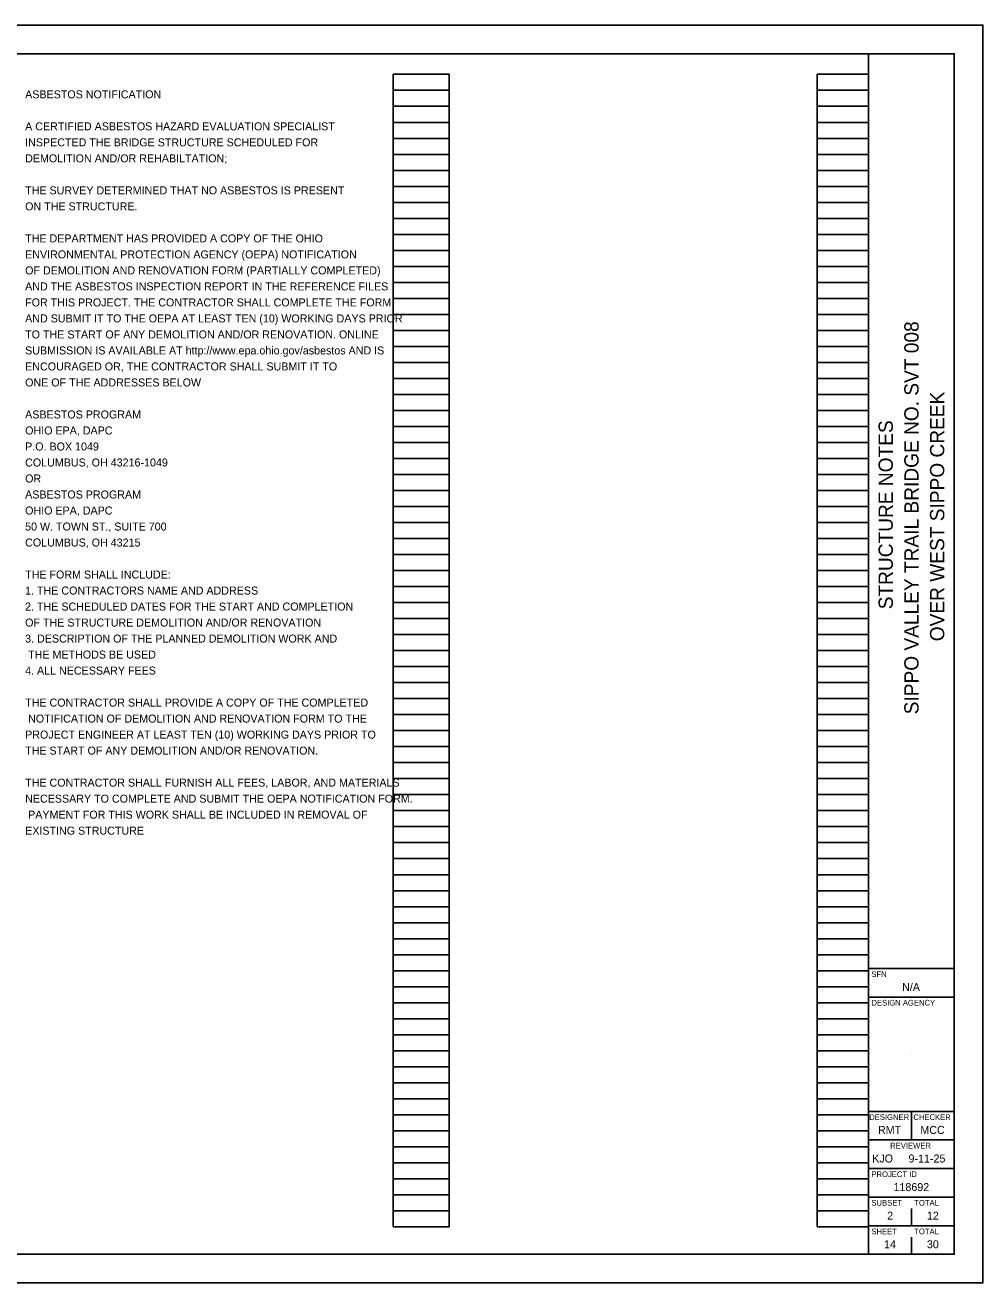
# Model space of a CAD drawing. Extents: x 0 to 34, y 0 to 22.
# Drawn here: x 17.24 to 34, y 0 to 22 of the extents above; entities that cross this region are included whole.
import ezdxf

# ---------------------------------------------------------------- set-up
doc = ezdxf.new("R2010")
doc.units = 0
for name, color, linetype in [('SH_Border', 7, 'Continuous'), ('SH_Cut_Line', 7, 'Continuous'), ('SH_Data', 7, 'Continuous'), ('SH_Text', 7, 'Continuous')]:
    doc.layers.add(name, color=color, linetype=linetype)

msp = doc.modelspace()

# ---------------------------------------------------------------- linework, layer by layer
at = {"layer": 'SH_Border'}
for p, q in [((32, 0.5), (32, 21.5)), ((32, 5.5), (33.5, 5.5)), ((32, 5), (33.5, 5)), ((32, 3), (33.5, 3)), ((32.75, 3), (32.75, 2.5)), ((32, 2.5), (33.5, 2.5)), ((32, 2), (33.5, 2)), ((32, 1.5), (33.5, 1.5)), ((32, 1), (33.5, 1))]:
    msp.add_line(p, q, dxfattribs=at)
msp.add_lwpolyline([(1.5, 21.5), (33.5, 21.5), (33.5, 0.5), (1.5, 0.5)], close=True, dxfattribs=at)
at = {"layer": 'SH_Cut_Line'}
msp.add_lwpolyline([(0, 0), (34, 0), (34, 22), (0, 22)], close=True, dxfattribs=at)
at = {"layer": 'SH_Data'}
for p, q in [((23.68, 0.98), (23.68, 21.14)), ((23.68, 21.14), (24.66, 21.14)), ((24.66, 0.98), (24.66, 21.14)), ((31.1, 0.98), (31.1, 21.14)), ((31.1, 21.14), (32, 21.14)), ((32, 0.98), (32, 21.14)), ((23.68, 20.86), (24.66, 20.86)), ((31.1, 20.86), (32, 20.86)), ((23.68, 20.58), (24.66, 20.58)), ((31.1, 20.58), (32, 20.58)), ((23.68, 20.3), (24.66, 20.3)), ((31.1, 20.3), (32, 20.3)), ((23.68, 20.02), (24.66, 20.02)), ((31.1, 20.02), (32, 20.02)), ((23.68, 19.74), (24.66, 19.74)), ((31.1, 19.74), (32, 19.74)), ((23.68, 19.46), (24.66, 19.46)), ((31.1, 19.46), (32, 19.46)), ((23.68, 19.18), (24.66, 19.18)), ((31.1, 19.18), (32, 19.18)), ((23.68, 18.9), (24.66, 18.9)), ((31.1, 18.9), (32, 18.9)), ((23.68, 18.62), (24.66, 18.62)), ((31.1, 18.62), (32, 18.62)), ((23.68, 18.34), (24.66, 18.34)), ((31.1, 18.34), (32, 18.34)), ((23.68, 18.06), (24.66, 18.06)), ((31.1, 18.06), (32, 18.06)), ((23.68, 17.78), (24.66, 17.78)), ((31.1, 17.78), (32, 17.78)), ((23.68, 17.5), (24.66, 17.5)), ((31.1, 17.5), (32, 17.5)), ((23.68, 17.22), (24.66, 17.22)), ((31.1, 17.22), (32, 17.22)), ((23.68, 16.94), (24.66, 16.94)), ((31.1, 16.94), (32, 16.94)), ((23.68, 16.66), (24.66, 16.66)), ((31.1, 16.66), (32, 16.66)), ((23.68, 16.38), (24.66, 16.38)), ((31.1, 16.38), (32, 16.38)), ((23.68, 16.1), (24.66, 16.1)), ((31.1, 16.1), (32, 16.1)), ((23.68, 15.82), (24.66, 15.82)), ((31.1, 15.82), (32, 15.82)), ((23.68, 15.54), (24.66, 15.54)), ((31.1, 15.54), (32, 15.54)), ((23.68, 15.26), (24.66, 15.26)), ((31.1, 15.26), (32, 15.26)), ((23.68, 14.98), (24.66, 14.98)), ((31.1, 14.98), (32, 14.98)), ((23.68, 14.7), (24.66, 14.7)), ((31.1, 14.7), (32, 14.7)), ((23.68, 14.42), (24.66, 14.42)), ((31.1, 14.42), (32, 14.42)), ((23.68, 14.14), (24.66, 14.14)), ((31.1, 14.14), (32, 14.14)), ((23.68, 13.86), (24.66, 13.86)), ((31.1, 13.86), (32, 13.86)), ((23.68, 13.58), (24.66, 13.58)), ((31.1, 13.58), (32, 13.58)), ((23.68, 13.3), (24.66, 13.3)), ((31.1, 13.3), (32, 13.3)), ((23.68, 13.02), (24.66, 13.02)), ((31.1, 13.02), (32, 13.02)), ((23.68, 12.74), (24.66, 12.74)), ((31.1, 12.74), (32, 12.74)), ((23.68, 12.46), (24.66, 12.46)), ((31.1, 12.46), (32, 12.46)), ((23.68, 12.18), (24.66, 12.18)), ((31.1, 12.18), (32, 12.18)), ((23.68, 11.9), (24.66, 11.9)), ((31.1, 11.9), (32, 11.9)), ((23.68, 11.62), (24.66, 11.62)), ((31.1, 11.62), (32, 11.62)), ((23.68, 11.34), (24.66, 11.34)), ((31.1, 11.34), (32, 11.34)), ((23.68, 11.06), (24.66, 11.06)), ((31.1, 11.06), (32, 11.06)), ((23.68, 10.78), (24.66, 10.78)), ((31.1, 10.78), (32, 10.78)), ((23.68, 10.5), (24.66, 10.5)), ((31.1, 10.5), (32, 10.5)), ((23.68, 10.22), (24.66, 10.22)), ((31.1, 10.22), (32, 10.22)), ((23.68, 9.94), (24.66, 9.94)), ((31.1, 9.94), (32, 9.94)), ((23.68, 9.66), (24.66, 9.66)), ((31.1, 9.66), (32, 9.66)), ((23.68, 9.38), (24.66, 9.38)), ((31.1, 9.38), (32, 9.38)), ((23.68, 9.1), (24.66, 9.1)), ((31.1, 9.1), (32, 9.1)), ((23.68, 8.82), (24.66, 8.82)), ((31.1, 8.82), (32, 8.82)), ((23.68, 8.54), (24.66, 8.54)), ((31.1, 8.54), (32, 8.54)), ((23.68, 8.26), (24.66, 8.26)), ((31.1, 8.26), (32, 8.26)), ((23.68, 7.98), (24.66, 7.98)), ((31.1, 7.98), (32, 7.98)), ((23.68, 7.7), (24.66, 7.7)), ((31.1, 7.7), (32, 7.7)), ((23.68, 7.42), (24.66, 7.42)), ((31.1, 7.42), (32, 7.42)), ((23.68, 7.14), (24.66, 7.14)), ((31.1, 7.14), (32, 7.14)), ((23.68, 6.86), (24.66, 6.86)), ((31.1, 6.86), (32, 6.86)), ((23.68, 6.58), (24.66, 6.58)), ((31.1, 6.58), (32, 6.58)), ((23.68, 6.3), (24.66, 6.3)), ((31.1, 6.3), (32, 6.3)), ((23.68, 6.02), (24.66, 6.02)), ((31.1, 6.02), (32, 6.02)), ((23.68, 5.74), (24.66, 5.74)), ((31.1, 5.74), (32, 5.74)), ((23.68, 5.46), (24.66, 5.46)), ((31.1, 5.46), (32, 5.46)), ((23.68, 5.18), (24.66, 5.18)), ((31.1, 5.18), (32, 5.18)), ((23.68, 4.9), (24.66, 4.9)), ((31.1, 4.9), (32, 4.9)), ((23.68, 4.62), (24.66, 4.62)), ((31.1, 4.62), (32, 4.62)), ((23.68, 4.34), (24.66, 4.34)), ((31.1, 4.34), (32, 4.34)), ((23.68, 4.06), (24.66, 4.06)), ((31.1, 4.06), (32, 4.06)), ((32.75, 4), (32.75, 4)), ((23.68, 3.78), (24.66, 3.78)), ((31.1, 3.78), (32, 3.78)), ((23.68, 3.5), (24.66, 3.5)), ((31.1, 3.5), (32, 3.5)), ((23.68, 3.22), (24.66, 3.22)), ((31.1, 3.22), (32, 3.22)), ((23.68, 2.94), (24.66, 2.94)), ((31.1, 2.94), (32, 2.94)), ((23.68, 2.66), (24.66, 2.66)), ((31.1, 2.66), (32, 2.66)), ((23.68, 2.38), (24.66, 2.38)), ((31.1, 2.38), (32, 2.38)), ((23.68, 2.1), (24.66, 2.1)), ((31.1, 2.1), (32, 2.1)), ((23.68, 1.82), (24.66, 1.82)), ((31.1, 1.82), (32, 1.82)), ((23.68, 1.54), (24.66, 1.54)), ((31.1, 1.54), (32, 1.54)), ((23.68, 1.26), (24.66, 1.26)), ((31.1, 1.26), (32, 1.26)), ((32.75, 1), (32.75, 1.3)), ((23.68, 0.98), (24.66, 0.98)), ((31.1, 0.98), (32, 0.98)), ((32.375, 0.675), (32.375, 0.675)), ((32.75, 0.5), (32.75, 0.8))]:
    msp.add_line(p, q, dxfattribs=at)

# ---------------------------------------------------------------- texts
for s, p in [('SIPPO VALLEY TRAIL BRIDGE NO. SVT 008', (32.875, 9.945)), ('OVER WEST SIPPO CREEK', (33.325, 11.223)), ('STRUCTURE NOTES', (32.425, 11.782))]:
    msp.add_text(s, height=0.25, rotation=90, dxfattribs=at).set_placement(p)
for s, height, p in [('SFN', 0.1, (32.05, 5.35)), ('N/A', 0.14, (32.587, 5.105)), ('DESIGN AGENCY', 0.1, (32.05, 4.85)), ('DESIGNER', 0.1, (32.011, 2.85)), ('CHECKER', 0.1, (32.784, 2.85)), ('RMT', 0.14, (32.165, 2.605)), ('MCC', 0.14, (32.906, 2.605)), ('REVIEWER', 0.1, (32.378, 2.35)), ('KJO', 0.14, (32.064, 2.105)), ('9-11-25', 0.14, (32.699, 2.105)), ('PROJECT ID', 0.1, (32.05, 1.85)), ('118692', 0.14, (32.436, 1.605)), ('SUBSET', 0.1, (32.05, 1.35)), ('TOTAL', 0.1, (32.8, 1.35)), ('2', 0.14, (32.326, 1.105)), ('12', 0.14, (33.021, 1.105)), ('SHEET', 0.1, (32.05, 0.85)), ('TOTAL', 0.1, (32.8, 0.85)), ('14', 0.14, (32.271, 0.605)), ('30', 0.14, (33.021, 0.605))]:
    msp.add_text(s, height=height, dxfattribs=at).set_placement(p)
at = {"layer": 'SH_Text'}
for s, p in [('ASBESTOS NOTIFICATION', (17.24, 20.72)), ('A CERTIFIED ASBESTOS HAZARD EVALUATION SPECIALIST ', (17.24, 20.16)), ('INSPECTED THE BRIDGE STRUCTURE SCHEDULED FOR ', (17.24, 19.88)), ('DEMOLITION AND/OR REHABILTATION;', (17.24, 19.6)), ('THE SURVEY DETERMINED THAT NO ASBESTOS IS PRESENT', (17.24, 19.04)), ('ON THE STRUCTURE.', (17.24, 18.76)), ('THE DEPARTMENT HAS PROVIDED A COPY OF THE OHIO ', (17.24, 18.2)), ('ENVIRONMENTAL PROTECTION AGENCY (OEPA) NOTIFICATION ', (17.24, 17.92)), ('OF DEMOLITION AND RENOVATION FORM (PARTIALLY COMPLETED) ', (17.24, 17.64)), ('AND THE ASBESTOS INSPECTION REPORT IN THE REFERENCE FILES ', (17.24, 17.36)), ('FOR THIS PROJECT. THE CONTRACTOR SHALL COMPLETE THE FORM ', (17.24, 17.08)), ('AND SUBMIT IT TO THE OEPA AT LEAST TEN (10) WORKING DAYS PRIOR ', (17.24, 16.8)), ('TO THE START OF ANY DEMOLITION AND/OR RENOVATION. ONLINE ', (17.24, 16.52)), ('SUBMISSION IS AVAILABLE AT http://www.epa.ohio.gov/asbestos AND IS ', (17.24, 16.24)), ('ENCOURAGED OR, THE CONTRACTOR SHALL SUBMIT IT TO ', (17.24, 15.96)), ('ONE OF THE ADDRESSES BELOW ', (17.24, 15.68)), ('ASBESTOS PROGRAM ', (17.24, 15.12)), ('OHIO EPA, DAPC ', (17.24, 14.84)), ('P.O. BOX 1049', (17.24, 14.56)), ('COLUMBUS, OH 43216-1049', (17.24, 14.28)), ('OR', (17.24, 14)), ('ASBESTOS PROGRAM', (17.24, 13.72)), ('OHIO EPA, DAPC ', (17.24, 13.44)), ('50 W. TOWN ST., SUITE 700', (17.24, 13.16)), ('COLUMBUS, OH 43215', (17.24, 12.88)), ('THE FORM SHALL INCLUDE: ', (17.24, 12.32)), ('1. THE CONTRACTORS NAME AND ADDRESS', (17.24, 12.04)), ('2. THE SCHEDULED DATES FOR THE START AND COMPLETION', (17.24, 11.76)), ('OF THE STRUCTURE DEMOLITION AND/OR RENOVATION', (17.24, 11.48)), ('3. DESCRIPTION OF THE PLANNED DEMOLITION WORK AND', (17.24, 11.2)), (' THE METHODS BE USED', (17.24, 10.92)), ('4. ALL NECESSARY FEES', (17.24, 10.64)), ('THE CONTRACTOR SHALL PROVIDE A COPY OF THE COMPLETED', (17.24, 10.08)), (' NOTIFICATION OF DEMOLITION AND RENOVATION FORM TO THE ', (17.24, 9.8)), ('PROJECT ENGINEER AT LEAST TEN (10) WORKING DAYS PRIOR TO ', (17.24, 9.52)), ('THE START OF ANY DEMOLITION AND/OR RENOVATION. ', (17.24, 9.24)), ('THE CONTRACTOR SHALL FURNISH ALL FEES, LABOR, AND MATERIALS ', (17.24, 8.68)), ('NECESSARY TO COMPLETE AND SUBMIT THE OEPA NOTIFICATION FORM.', (17.24, 8.4)), (' PAYMENT FOR THIS WORK SHALL BE INCLUDED IN REMOVAL OF ', (17.24, 8.12)), ('EXISTING STRUCTURE', (17.24, 7.84))]:
    msp.add_text(s, height=0.14, dxfattribs=at).set_placement(p)

doc.saveas('drawing.dxf')
